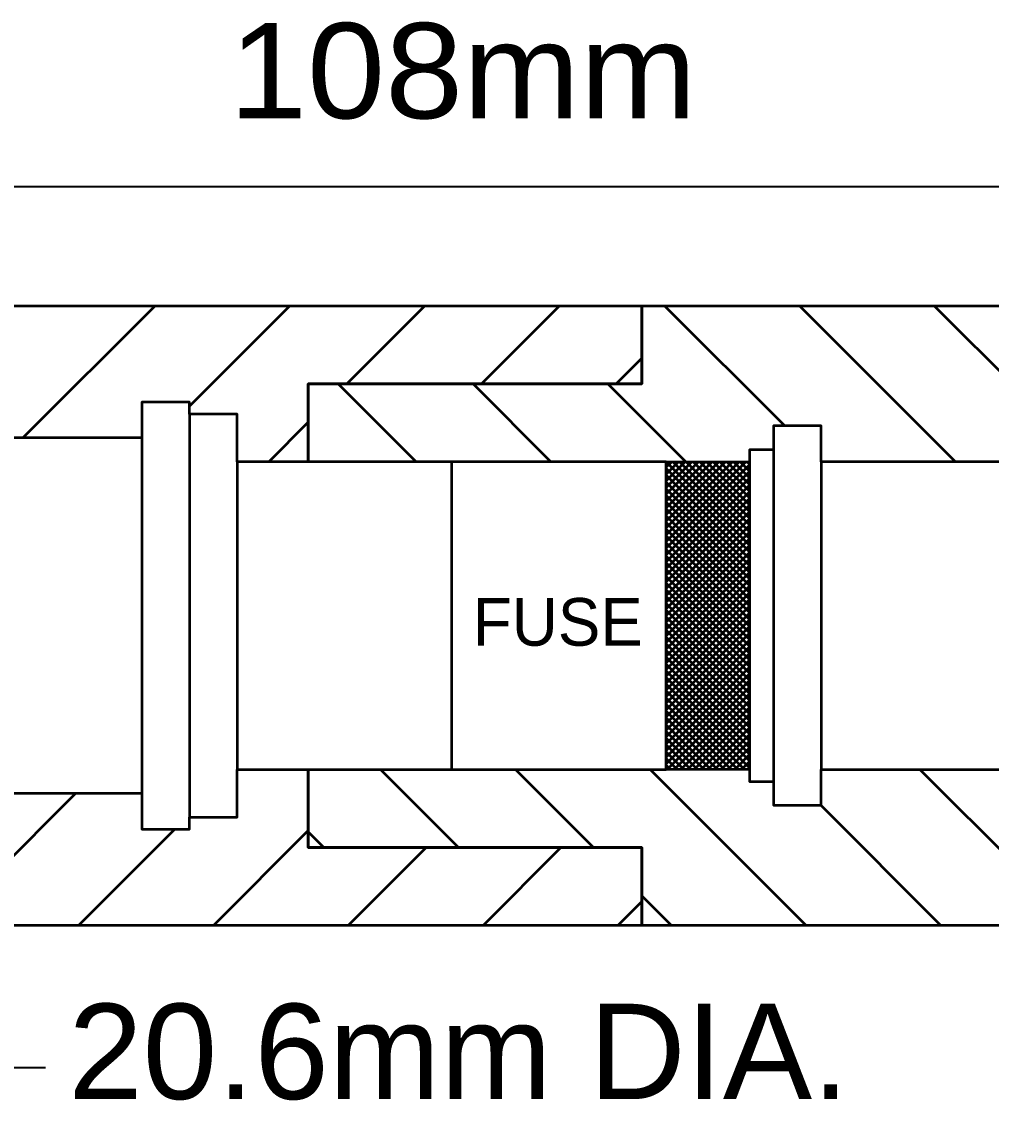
# Model space of a CAD drawing. Extents: x -32 to 824, y -6 to 538.
# Drawn here: x 605.1 to 629.52, y 272.11 to 299.27 of the extents above; entities that cross this region are included whole.
import ezdxf

# ---------------------------------------------------------------- set-up
doc = ezdxf.new("R2010")
doc.units = 0
doc.header["$LTSCALE"] = 1.1
doc.layers.add('1', color=7, linetype='Continuous', lineweight=53)

msp = doc.modelspace()

# ---------------------------------------------------------------- linework, layer by layer
at = {"layer": '1', "lineweight": 35}
for p, q in [((579.92, 295.113), (654.32, 295.113)), ((604.507, 272.938), (605.706, 272.938))]:
    msp.add_line(p, q, dxfattribs=at)
at = {"layer": '1'}
for p, q in [((605.137, 288.786), (608.463, 292.113)), ((609.331, 289.586), (611.858, 292.113)), ((613.288, 290.15), (615.252, 292.113)), ((616.683, 290.15), (618.646, 292.113)), ((624.321, 289.087), (621.294, 292.113)), ((628.615, 288.187), (624.688, 292.113)), ((633.106, 287.089), (628.083, 292.113)), ((620.077, 290.15), (620.72, 290.793)), ((615.038, 288.187), (613.075, 290.15)), ((618.432, 288.187), (616.469, 290.15)), ((621.826, 288.187), (619.863, 290.15)), ((609.331, 289.387), (609.331, 279.239)), ((611.325, 288.187), (612.32, 289.181)), ((608.131, 288.786), (608.131, 279.839)), ((624.031, 288.487), (624.031, 280.139)), ((610.531, 288.187), (610.531, 280.439)), ((621.331, 288.187), (612.32, 288.187)), ((615.931, 288.187), (615.931, 280.439)), ((621.331, 288.046), (621.472, 288.187)), ((621.331, 287.876), (621.641, 288.187)), ((621.331, 287.707), (621.811, 288.187)), ((621.331, 287.537), (621.981, 288.187)), ((621.331, 287.367), (622.15, 288.187)), ((621.331, 287.197), (622.32, 288.187)), ((621.331, 287.028), (622.49, 288.187)), ((621.331, 286.858), (622.66, 288.187)), ((621.331, 286.688), (622.829, 288.187)), ((621.331, 286.519), (622.999, 288.187)), ((621.331, 286.349), (623.169, 288.187)), ((621.331, 286.179), (623.338, 288.187)), ((623.431, 286.085), (621.331, 288.185)), ((623.431, 286.254), (621.499, 288.187)), ((623.431, 286.424), (621.669, 288.187)), ((623.431, 286.594), (621.838, 288.187)), ((623.431, 286.763), (622.008, 288.187)), ((623.431, 286.933), (622.178, 288.187)), ((623.431, 287.103), (622.348, 288.187)), ((623.431, 287.273), (622.517, 288.187)), ((623.431, 287.442), (622.687, 288.187)), ((623.431, 287.612), (622.857, 288.187)), ((623.431, 287.782), (623.026, 288.187)), ((623.431, 287.951), (623.196, 288.187)), ((623.431, 288.121), (623.366, 288.187)), ((625.231, 288.187), (625.231, 280.439)), ((621.331, 286.01), (623.431, 288.11)), ((623.431, 285.915), (621.331, 288.015)), ((621.331, 285.84), (623.431, 287.94)), ((623.431, 285.745), (621.331, 287.845)), ((621.331, 285.67), (623.431, 287.77)), ((623.431, 285.576), (621.331, 287.675)), ((621.331, 285.5), (623.431, 287.6)), ((623.431, 285.406), (621.331, 287.506)), ((621.331, 285.331), (623.431, 287.431)), ((623.431, 285.236), (621.331, 287.336)), ((621.331, 285.161), (623.431, 287.261)), ((623.431, 285.066), (621.331, 287.166)), ((621.331, 284.991), (623.431, 287.091)), ((623.431, 284.897), (621.331, 286.997)), ((621.331, 284.822), (623.431, 286.922)), ((623.431, 284.727), (621.331, 286.827)), ((621.331, 284.652), (623.431, 286.752)), ((623.431, 284.557), (621.331, 286.657)), ((621.331, 284.482), (623.431, 286.582)), ((623.431, 284.388), (621.331, 286.488)), ((621.331, 284.312), (623.431, 286.413)), ((623.431, 284.218), (621.331, 286.318)), ((621.331, 284.143), (623.431, 286.243)), ((623.431, 284.048), (621.331, 286.148)), ((621.331, 283.973), (623.431, 286.073)), ((623.431, 283.879), (621.331, 285.978)), ((621.331, 283.803), (623.431, 285.903)), ((623.431, 283.709), (621.331, 285.809)), ((621.331, 283.634), (623.431, 285.734)), ((623.431, 283.539), (621.331, 285.639)), ((621.331, 283.464), (623.431, 285.564)), ((623.431, 283.369), (621.331, 285.469)), ((621.331, 283.294), (623.431, 285.394)), ((623.431, 283.2), (621.331, 285.3)), ((621.331, 283.125), (623.431, 285.225)), ((623.431, 283.03), (621.331, 285.13)), ((621.331, 282.955), (623.431, 285.055)), ((623.431, 282.86), (621.331, 284.96)), ((621.331, 282.785), (623.431, 284.885)), ((623.431, 282.69), (621.331, 284.791)), ((621.331, 282.615), (623.431, 284.715)), ((623.431, 282.521), (621.331, 284.621)), ((621.331, 282.446), (623.431, 284.546)), ((623.431, 282.351), (621.331, 284.451)), ((621.331, 282.276), (623.431, 284.376)), ((623.431, 282.181), (621.331, 284.281)), ((621.331, 282.106), (623.431, 284.206)), ((623.431, 282.012), (621.331, 284.112)), ((621.331, 281.937), (623.431, 284.037)), ((623.431, 281.842), (621.331, 283.942)), ((621.331, 281.767), (623.431, 283.867)), ((623.431, 281.672), (621.331, 283.772)), ((621.331, 281.597), (623.431, 283.697)), ((623.431, 281.503), (621.331, 283.603)), ((621.331, 281.428), (623.431, 283.528)), ((623.431, 281.333), (621.331, 283.433)), ((621.331, 281.258), (623.431, 283.358)), ((623.431, 281.163), (621.331, 283.263)), ((621.331, 281.088), (623.431, 283.188)), ((623.431, 280.994), (621.331, 283.094)), ((621.331, 280.918), (623.431, 283.018)), ((623.431, 280.824), (621.331, 282.924)), ((621.331, 280.749), (623.431, 282.849)), ((623.431, 280.654), (621.331, 282.754)), ((621.331, 280.579), (623.431, 282.679)), ((623.431, 280.484), (621.331, 282.584)), ((621.361, 280.439), (623.431, 282.509)), ((623.307, 280.439), (621.331, 282.415)), ((623.137, 280.439), (621.331, 282.245)), ((621.531, 280.439), (623.431, 282.339)), ((621.7, 280.439), (623.431, 282.17)), ((622.967, 280.439), (621.331, 282.075)), ((622.798, 280.439), (621.331, 281.906)), ((621.87, 280.439), (623.431, 282)), ((622.628, 280.439), (621.331, 281.736)), ((622.04, 280.439), (623.431, 281.83)), ((622.209, 280.439), (623.431, 281.661)), ((622.458, 280.439), (621.331, 281.566)), ((622.289, 280.439), (621.331, 281.396)), ((622.379, 280.439), (623.431, 281.491)), ((622.119, 280.439), (621.331, 281.227)), ((622.549, 280.439), (623.431, 281.321)), ((622.718, 280.439), (623.431, 281.152)), ((621.949, 280.439), (621.331, 281.057)), ((621.779, 280.439), (621.331, 280.887)), ((622.888, 280.439), (623.431, 280.982)), ((621.61, 280.439), (621.331, 280.718)), ((621.44, 280.439), (621.331, 280.548)), ((623.058, 280.439), (623.431, 280.812)), ((623.228, 280.439), (623.431, 280.643)), ((616.104, 278.476), (614.141, 280.439)), ((619.499, 278.476), (617.535, 280.439)), ((624.856, 276.513), (620.93, 280.439)), ((623.397, 280.439), (623.431, 280.473)), ((631.644, 276.513), (627.718, 280.439)), ((603.144, 276.513), (606.47, 279.839)), ((628.25, 276.513), (625.224, 279.539)), ((606.538, 276.513), (608.965, 278.939)), ((609.932, 276.513), (612.32, 278.9)), ((612.71, 278.476), (612.32, 278.866)), ((613.327, 276.513), (615.29, 278.476)), ((616.721, 276.513), (618.684, 278.476)), ((620.115, 276.513), (620.72, 277.118)), ((621.462, 276.513), (620.72, 277.254))]:
    msp.add_line(p, q, dxfattribs=at)
for points in [[(579.92, 286.113), (579.92, 289.113), (589.52, 289.113), (596.72, 291.213), (596.72, 292.113), (620.72, 292.113), (620.72, 290.15), (612.32, 290.15), (612.32, 288.187), (610.531, 288.187), (610.531, 289.387), (609.331, 289.387), (609.331, 289.687), (608.131, 289.687), (608.131, 288.786), (603.931, 288.786), (603.109, 287.913)], [(612.32, 288.187), (612.32, 290.15), (620.72, 290.15), (620.72, 292.113), (637.52, 292.113), (637.52, 291.213), (644.72, 289.113), (654.32, 289.113), (654.32, 286.113)], [(630.031, 288.187), (625.231, 288.187), (625.231, 289.087), (624.031, 289.087), (624.031, 288.487), (623.431, 288.487), (623.431, 288.187)], [(654.32, 282.513), (654.32, 279.513), (644.72, 279.513), (637.52, 277.413), (637.52, 276.513), (620.72, 276.513), (620.72, 278.476), (612.32, 278.476)], [(603.109, 280.713), (603.931, 279.839), (608.131, 279.839), (608.131, 278.939), (609.331, 278.939), (609.331, 279.239), (610.531, 279.239), (610.531, 280.439), (612.32, 280.439), (612.32, 278.476), (620.72, 278.476), (620.72, 276.513), (596.72, 276.513), (596.72, 277.413), (589.52, 279.513), (579.92, 279.513)], [(612.32, 278.476), (612.32, 280.439), (621.331, 280.439)], [(623.431, 280.439), (623.431, 280.139), (624.031, 280.139), (624.031, 279.539), (625.231, 279.539), (625.231, 280.439), (630.031, 280.439)]]:
    msp.add_lwpolyline(points, dxfattribs=at)
msp.add_lwpolyline([(621.331, 280.439), (621.331, 288.187), (623.431, 288.187), (623.431, 280.439)], close=True, dxfattribs=at)

# ---------------------------------------------------------------- texts
for s, width, p in [('108mm', 1.1, (610.328, 296.83)), ('20.6mm DIA.', 1.05, (606.28, 272.142))]:
    msp.add_text(s, height=2.4, dxfattribs=dict(at, width=width)).set_placement(p)
msp.add_text('FUSE', height=1.2, dxfattribs=at).set_placement((616.465, 283.554))

doc.saveas('drawing.dxf')
